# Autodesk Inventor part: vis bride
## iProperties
Created: 2002-03
Part Number: vis bride
Material: Par défaut
Document SubType Name: Modélisation
Designer: User
Control State: 0
Master: False
Checked Out: False
Shininess: 20.0
Length Units: 11269
Angle Units: 11279
Time Units: 11290
Mass Units: 11283
Length Display Precision: 3
Angle Display Precision: 2
Density: 0.0
Volumn: 0.0
Area: 0.0
PropertySet Name: Model Information
Author: User
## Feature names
1. Extrusion1
2. Extrusion2
3. Chanfrein1 [Chamfer]
4. Congé1 [Fillet]
5. Extrusion3
